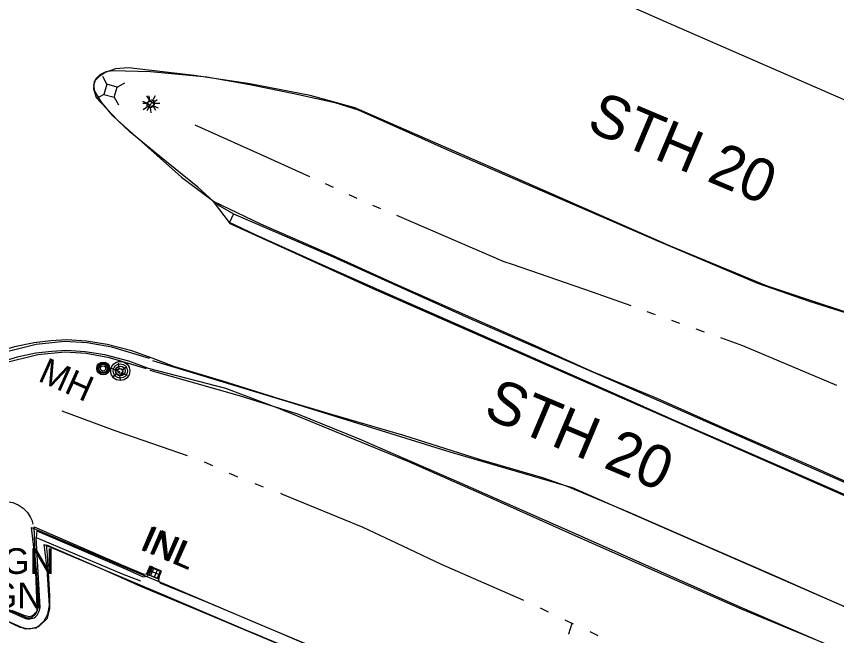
# Model space of a CAD drawing. Extents: x 588843 to 2552415, y 180129 to 269402.
# Drawn here: x 594846.6 to 595038, y 185001.1 to 185145.6 of the extents above; entities that cross this region are included whole.
import ezdxf

# ---------------------------------------------------------------- set-up
doc = ezdxf.new("R2010")
doc.units = 0
for name, color, linetype in [('Default', 7, 'Continuous'), ('E_DRN', 7, 'Continuous'), ('E_DRN_Text', 7, 'Continuous'), ('E_DWY', 7, 'Continuous'), ('E_LTG', 7, 'Continuous'), ('E_MISCPROP', 7, 'Continuous'), ('E_MISCPROP_Planter', 7, 'Continuous'), ('E_RDWY', 7, 'Continuous'), ('E_RDWY_AsphConc', 7, 'Continuous'), ('E_RDWY_C_and_G', 7, 'Continuous'), ('E_RDWY_Gravel', 7, 'Continuous'), ('E_RDWY_Text', 7, 'Continuous'), ('E_SGN', 7, 'Continuous'), ('E_UTL_AG_Bold', 7, 'Continuous'), ('E_UTL_MH', 7, 'Continuous'), ('E_UTL_MH_Text', 7, 'Continuous'), ('E_WTR_P', 7, 'Continuous')]:
    doc.layers.add(name, color=color, linetype=linetype)

# ---------------------------------------------------------------- blocks, each defined once
blk = doc.blocks.new('INLO')
at = {"layer": 'E_DRN'}
for p, q in [((2, -4), (2, 0)), ((4, -4), (4, 0)), ((6, -2), (0, -2))]:
    blk.add_line(p, q, dxfattribs=at)
blk.add_lwpolyline([(0, -4), (6, -4), (6, 0), (0, 0), (0, -4)], close=True, dxfattribs=at)
blk = doc.blocks.new('INLT_22')
at = {"layer": 'E_DRN_Text'}
blk.add_text('INL', height=12, dxfattribs=at).set_placement((-11.03, -6))
blk = doc.blocks.new('MHO')
at = {"layer": 'Default'}
for centre, radius in [((0.08, -0.12), 3), ((0.08, -0.12), 2.43), ((0.07, -0.15), 1.94), ((0.02, -0.16), 1.21)]:
    blk.add_circle(centre, radius, dxfattribs=at)
blk = doc.blocks.new('MHT')
at = {"layer": 'E_UTL_MH_Text'}
blk.add_text('MH', height=12, dxfattribs=at).set_placement((-9.81, -6))
blk = doc.blocks.new('LPOL')
at = {"layer": 'Default'}
for p, q in [((-4, 0), (-1.5, 0)), ((-0.75, 1.3), (-2, 3.46)), ((0.75, 1.3), (2, 3.46)), ((1.5, 0), (4, 0)), ((-2, -3.46), (-0.75, -1.3)), ((2, -3.46), (0.75, -1.3))]:
    blk.add_line(p, q, dxfattribs=at)
for radius in [1.5, 1.5, 1.5, 0.125]:
    blk.add_circle((0, 0), radius, dxfattribs=at)
blk = doc.blocks.new('BSGN_1')
at = {"layer": 'Default'}
blk.add_text('SIGN', height=12, dxfattribs=at).set_placement((-18.56, -6))
blk = doc.blocks.new('POLE_3')
at = {"layer": 'E_MISCPROP'}
for radius in [14.6, 11, 7.32, 3.66]:
    blk.add_circle((0, 0), radius, dxfattribs=at)
blk = doc.blocks.new('LPOL_4')
at = {"layer": 'E_LTG'}
for p, q in [((-13.1, 0), (-4.9, 0)), ((-2.5, 4.3), (-6.6, 11.4)), ((2.5, 4.3), (6.6, 11.4)), ((4.9, 0), (13.1, 0)), ((-6.6, -11.4), (-2.5, -4.3)), ((6.6, -11.4), (2.5, -4.3))]:
    blk.add_line(p, q, dxfattribs=at)
for radius in [4.92, 4.92, 4.92, 0.41]:
    blk.add_circle((0, 0), radius, dxfattribs=at)
blk = doc.blocks.new('INLT_29_2')
at = {"layer": 'E_DRN_Text'}
blk.add_text('INL', height=39.37, dxfattribs=at).set_placement((-36.2, -19.7))
blk = doc.blocks.new('PED_3')
at = {"layer": 'E_UTL_AG_Bold'}
for p, q in [((-8.2, 8.2), (-17.5, 17.5)), ((8.2, 8.2), (17.5, 17.5)), ((-8.2, -8.2), (-17.5, -17.5)), ((8.2, -8.2), (17.5, -17.5))]:
    blk.add_line(p, q, dxfattribs=at)
blk.add_lwpolyline([(-8.2, -8.2), (8.2, -8.2), (8.2, 8.2), (-8.2, 8.2)], close=True, dxfattribs=at)

msp = doc.modelspace()

# ---------------------------------------------------------------- linework, layer by layer
at = {"layer": 'E_DRN'}
msp.add_lwpolyline([(594878.27, 185016.85), (594880.17, 185016.1), (594879.52, 185014.44), (594877.62, 185015.19)], close=True, dxfattribs=at)
at = {"layer": 'E_DWY'}
for points in [[(594851.32, 185016.44), (594850.15, 185026.3), (594876.17, 185015.26), (594882.3, 185012.69), (594902.2, 185004.23)], [(594842.02, 185005.56), (594847.42, 185003.01), (594849.69, 185002.62), (594851.91, 185003.19), (594853.88, 185005.11), (594854.47, 185007.32), (594854.46, 185010.36), (594853.91, 185019.95), (594853.68, 185022.26), (594866.41, 185016.76), (594875.58, 185012.63)], [(594853.8, 185016.73), (594853.14, 185022.31), (594881.32, 185010.39), (594901.22, 185001.93)], [(594812.39, 184960.2), (594816.48, 184971.63), (594821.65, 184984.69), (594829.53, 185003.63), (594833.21, 185012.2), (594849.12, 185005.19), (594850.27, 185005.27), (594851.11, 185006.05), (594851.57, 185006.94), (594851.86, 185008.3), (594851.32, 185016.44)], [(594814.75, 184959.36), (594818.82, 184970.75), (594823.97, 184983.75), (594831.83, 185002.65), (594834.51, 185008.89), (594848.68, 185002.65), (594851.33, 185002.84), (594853.13, 185004.52), (594853.95, 185006.1), (594854.37, 185008.12), (594853.81, 185016.6)], [(594880.13, 185013.4), (594879.84, 185013.96), (594880.08, 185015.33)], [(594875.58, 185012.63), (594890, 185006.61), (594906.61, 184999.61), (594919.3, 184994.16), (594934.73, 184987.79), (594947.71, 184982.35), (594948.54, 184981.95), (594949.63, 184959.24), (594949.85, 184954.76), (594950.38, 184952.7), (594951.56, 184950.95), (594953.31, 184949.6), (594955.43, 184949.05), (594957.6, 184949.36), (594973.26, 184958.44), (594974.11, 184938.99), (594974.84, 184926.05), (594975.21, 184917.53)], [(594880.13, 185013.4), (594890.96, 185008.92), (594907.59, 185001.91), (594920.27, 184996.47), (594935.69, 184990.1), (594948.74, 184984.63), (594950.96, 184983.54), (594952.13, 184959.36), (594952.34, 184955.13), (594952.69, 184953.74), (594953.41, 184952.68), (594954.43, 184951.89), (594955.58, 184951.59), (594956.77, 184951.76), (594975.58, 184962.67), (594976.6, 184939.12), (594977.34, 184926.17), (594977.71, 184917.64)], [(594902.2, 185004.23), (594928.88, 184993.01), (594946.5, 184985.51), (594951.42, 184983.39), (594952.48, 184955.24), (594952.93, 184953.26), (594953.77, 184951.9), (594955.03, 184951.64), (594956.83, 184951.84), (594961.62, 184954.26), (594975.86, 184962.16), (594977.26, 184932.37)], [(594901.23, 185001.93), (594927.91, 184990.71), (594945.51, 184983.22), (594948.98, 184981.72), (594949.99, 184954.9), (594950.59, 184952.3), (594952.21, 184949.66), (594954.92, 184949.11), (594957.55, 184949.41), (594962.79, 184952.05), (594973.55, 184958.02), (594974.77, 184932.26)]]:
    msp.add_lwpolyline(points, dxfattribs=at)
at = {"layer": 'E_MISCPROP_Planter'}
msp.add_lwpolyline([(594831.77, 185013.9), (594837.81, 185029.35), (594838.62, 185030.36), (594839.59, 185031.22), (594839.59, 185031.22), (594840.52, 185031.78), (594841.53, 185032.14), (594841.53, 185032.14), (594844.01, 185032.45), (594844.01, 185032.45), (594845.78, 185032.17), (594845.78, 185032.17), (594847.07, 185031.6), (594848.23, 185030.8), (594848.23, 185030.8), (594849.19, 185029.82), (594849.94, 185028.66), (594849.94, 185028.66), (594850.21, 185028.01), (594850.21, 185028.01), (594850.44, 185027.07), (594850.44, 185027.07)], dxfattribs=at)
at = {"layer": 'E_RDWY'}
for points in [[(594953.31, 185166.36), (594958.15, 185162.28), (594975.56, 185154.43), (594999.99, 185143.55), (595034.76, 185128.38), (595068.45, 185113.72), (595097.34, 185101.25), (595121.56, 185090.33), (595130.22, 185086.62), (595134.71, 185084.42)], [(594925.9, 185124.17), (594915.18, 185127.16), (594901.1, 185129.86), (594888.15, 185131.83), (594872.8, 185133.66), (594869.76, 185133.4), (594867.37, 185132.55), (594865.85, 185131.55), (594864.81, 185130.42), (594864.64, 185128.73), (594865.28, 185126.7), (594870.22, 185121.39), (594885.15, 185108.11), (594894.17, 185101.33), (594897.33, 185099.5)], [(595049.2, 185029.86), (595032.18, 185037.35), (595016.49, 185044.18), (595000.22, 185051.32), (594985.89, 185057.65), (594969.81, 185064.77), (594952.53, 185072.36), (594931.31, 185081.72), (594915.85, 185088.59), (594902.43, 185094.62), (594896.4, 185097.5), (594892.65, 185102.39), (594888.98, 185105.77), (594880.03, 185112.97), (594873.11, 185118.65), (594869.14, 185122.44), (594866.48, 185125.57), (594864.94, 185128.17), (594864.74, 185129.6), (594865.19, 185131.08), (594866.21, 185132.08), (594867.55, 185132.75), (594869.06, 185133.03), (594877.96, 185132.75), (594891.11, 185131.49), (594901.08, 185129.72), (594911.75, 185127.57), (594920.96, 185125.49), (594926.41, 185123.84), (594947.09, 185114.58), (594965.39, 185106.61), (594983.19, 185098.92), (594996.06, 185093.29), (595008.35, 185088.08), (595019.6, 185083.37), (595031.64, 185079.16), (595047.2, 185074.24)], [(594925.9, 185124.17), (594958.5, 185109.94), (594999.16, 185092.06), (595021.58, 185082.77), (595050.38, 185073.2), (595081.02, 185063.61), (595102.72, 185056.02)], [(594897.33, 185099.5), (594896.3, 185097.34), (594929.83, 185082.12), (594970.2, 185064.32), (595016.88, 185043.89), (595058.26, 185025.7), (595093.29, 185010.35), (595106.31, 185004.68)], [(595050.7, 185003.11), (595036.24, 185009.41), (595021.57, 185015.87), (595005.62, 185022.78), (594989.44, 185029.87), (594975.03, 185035.94), (594969.71, 185037.84), (594954.73, 185042.17), (594937.03, 185047.81), (594919.92, 185052.73), (594908.19, 185056.29), (594894.77, 185060.43), (594883.38, 185063.87), (594878.29, 185065.81)], [(594878.43, 185065.29), (594911.2, 185055.3), (594947.8, 185044), (594976.33, 185035.64), (594988.52, 185030.3), (595035.74, 185009.62), (595076.71, 184991.76), (595101.16, 184980.97)]]:
    msp.add_lwpolyline(points, dxfattribs=at)
at = {"layer": 'E_RDWY_AsphConc'}
msp.add_lwpolyline([(594833.35, 185012.01), (594848.19, 185005.26), (594849.04, 185004.96), (594849.04, 185004.96), (594849.76, 185004.95), (594849.76, 185004.95), (594850.81, 185005.24), (594850.81, 185005.24), (594851.2, 185005.5), (594851.2, 185005.5), (594851.46, 185005.82), (594851.46, 185005.82), (594851.8, 185006.42), (594851.8, 185006.42), (594852.01, 185006.93), (594852.01, 185006.93), (594852.15, 185007.6), (594852.15, 185007.6), (594851.28, 185023.97)], dxfattribs=at)
at = {"layer": 'E_RDWY_C_and_G'}
for points in [[(594877.71, 185065.75), (594868.91, 185068.38), (594863.17, 185069.42), (594857.86, 185069.72), (594851.23, 185069.06), (594842.77, 185066.96), (594836.57, 185064.64), (594831.24, 185061.78), (594825.72, 185057.68), (594821.03, 185053.11), (594817.27, 185048.39), (594814.12, 185043.28), (594804.83, 185024.13)], [(594878.29, 185065.81), (594873.6, 185067.51), (594867.78, 185069.05), (594862.98, 185069.84), (594858.38, 185070.11), (594854.67, 185069.92), (594850.77, 185069.44), (594846.17, 185068.46), (594841.35, 185067.05), (594836.8, 185065.31), (594832.22, 185062.74), (594827.91, 185059.98), (594823.46, 185056.1), (594821.34, 185053.95)], [(594876.99, 185063.36), (594868.33, 185065.95), (594862.88, 185066.94), (594857.91, 185067.21), (594851.66, 185066.59), (594843.51, 185064.57), (594837.6, 185062.36), (594832.59, 185059.66), (594827.35, 185055.77), (594822.89, 185051.43), (594819.32, 185046.95), (594816.31, 185042.07), (594807.08, 185023.04)], [(594877.44, 185063.46), (594872.86, 185065.12), (594867.26, 185066.6), (594862.7, 185067.35), (594858.36, 185067.61), (594854.89, 185067.43), (594851.18, 185066.97), (594846.78, 185066.03), (594842.15, 185064.67), (594837.86, 185063.04), (594833.51, 185060.59), (594829.41, 185057.97), (594824.3, 185052.6)], [(594845.5, 185006.96), (594848.37, 185005.84), (594848.37, 185005.84), (594849.29, 185005.56), (594849.29, 185005.56), (594849.67, 185005.51), (594849.67, 185005.51), (594850.07, 185005.59), (594850.07, 185005.59), (594850.75, 185006.01), (594850.75, 185006.01), (594851.1, 185006.34), (594851.1, 185006.34), (594851.38, 185006.72), (594851.38, 185006.72), (594851.51, 185007.09), (594851.51, 185007.09), (594851.5, 185007.65), (594851.5, 185007.65), (594850.82, 185026.43), (594871.59, 185017.42), (594876.35, 185015.43), (594877.05, 185015.5), (594877.05, 185015.5), (594877.55, 185015.89), (594877.55, 185015.89), (594878.05, 185017.25), (594878.38, 185017.15)], [(594851.41, 185025.5), (594851.28, 185023.97), (594871.32, 185015.46), (594875.57, 185013.82)], [(594851.41, 185025.5), (594871.71, 185016.79), (594876.25, 185014.79), (594877.18, 185014.91), (594877.18, 185014.91), (594877.8, 185015.54), (594877.8, 185015.54), (594878.1, 185016.19), (594878.38, 185017.15)]]:
    msp.add_lwpolyline(points, dxfattribs=at)
at = {"layer": 'E_RDWY_Gravel'}
for points in [[(595048.4, 185033.3), (595032.11, 185040.59), (595011.9, 185049.39), (594996.16, 185056.38), (594980.77, 185062.83), (594966.82, 185069.09), (594952.68, 185075.32), (594935.11, 185083.12), (594920.43, 185089.79), (594903.67, 185097.13), (594892.65, 185102.39)], [(594897.33, 185099.5), (594919.84, 185089.79), (594952.31, 185075.17), (594998.39, 185055.12), (595039.68, 185036.96), (595083.25, 185017.84), (595107.08, 185007.74)], [(595052.68, 184991.66), (595035.98, 184998.92), (595015.83, 185007.26), (594997.64, 185015.28), (594976.31, 185024.69), (594956.73, 185033.45), (594938.19, 185041.65), (594920.92, 185048.72), (594907.85, 185054.11), (594895.48, 185058.78), (594877.44, 185063.46)], [(594877.78, 185063.02), (594898.63, 185057.15), (594912.24, 185052.85), (594926.64, 185046.99), (594949.85, 185036.86), (594978.4, 185024.29), (595015.45, 185007.75), (595046.08, 184994.58), (595082.47, 184978.64), (595101.48, 184970.64)]]:
    msp.add_lwpolyline(points, dxfattribs=at)
at = {"layer": 'E_WTR_P'}
for points in [[(594888.31, 185120.33), (594905.09, 185112.76), (594915.02, 185108.25)], [(594918.7, 185106.58), (594920.54, 185105.74)], [(594924.22, 185104.07), (594926.06, 185103.23)], [(594929.75, 185101.58), (594931.61, 185100.78)], [(594935.32, 185099.19), (594960.38, 185088.44), (594962.31, 185087.77)], [(594962.31, 185087.77), (594980.97, 185081.32), (594989.98, 185078.1)], [(594993.78, 185076.74), (594995.28, 185076.2), (594995.69, 185076.06)], [(594999.5, 185074.7), (595001.4, 185074.03)], [(595005.21, 185072.67), (595007.12, 185072)], [(595010.93, 185070.65), (595016.1, 185068.81), (595038.03, 185059.51)], [(594857.26, 185053.51), (594869.61, 185048.97), (594882.47, 185044.49), (594886.46, 185043.13)], [(594890.47, 185041.66), (594892.42, 185040.77)], [(594896.3, 185038.99), (594897.23, 185038.56), (594898.27, 185038.16)], [(594902.26, 185036.6), (594904.25, 185035.83)], [(594908.23, 185034.28), (594908.88, 185034.02), (594927.47, 185026.4), (594936.7, 185022.03)], [(594936.7, 185022.03), (594945.76, 185017.75), (594964.96, 185009.32)], [(594968.84, 185007.51), (594970.76, 185006.59)], [(594974.62, 185004.75), (594976.55, 185003.82)], [(594975.53, 185001.42), (594975.53, 185001.5), (594976.32, 185003.93)], [(594980.41, 185001.98), (594982.33, 185001.06), (594982.34, 185001.06)]]:
    msp.add_lwpolyline(points, dxfattribs=at)

# ---------------------------------------------------------------- block references
at = {"layer": 'E_DRN', "xscale": 0.5, "yscale": 0.5, "rotation": 157.10065989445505}
msp.add_blockref('INLO', (594879.74, 185014.3), dxfattribs=at)
at = {"layer": 'E_DRN_Text'}
for name, p, xscale, yscale, rotation in [('INLT_29_2', (594881.45, 185021.88), 0.1524003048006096, 0.1524003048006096, -22.831300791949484), ('INLT_22', (594881.8, 185021.88), 0.49999999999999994, 0.49999999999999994, -24.085783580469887)]:
    msp.add_blockref(name, p, dxfattribs=dict(at, xscale=xscale, yscale=yscale, rotation=rotation))
at = {"layer": 'E_LTG'}
for name, p, xscale, yscale, rotation in [('LPOL', (594877.87, 185125.07), 0.5, 0.5, -23.807133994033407), ('LPOL_4', (594878.13, 185125.38), 0.15240030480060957, 0.15240030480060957, 0.8014450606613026), ('LPOL', (594870.69, 185062.65), 0.49999999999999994, 0.49999999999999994, -24.085783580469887)]:
    msp.add_blockref(name, p, dxfattribs=dict(at, xscale=xscale, yscale=yscale, rotation=rotation))
at = {"layer": 'E_MISCPROP', "xscale": 0.15240030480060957, "yscale": 0.15240030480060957, "rotation": 0.8014450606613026}
msp.add_blockref('POLE_3', (594870.88, 185062.84), dxfattribs=at)
at = {"layer": 'E_SGN', "xscale": 0.5, "yscale": 0.5}
for p in [(594845.19, 185018.46), (594842.29, 185010.45)]:
    msp.add_blockref('BSGN_1', p, dxfattribs=at)
at = {"layer": 'E_UTL_AG_Bold', "xscale": 0.1524003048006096, "yscale": 0.1524003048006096, "rotation": -15.969778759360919}
msp.add_blockref('PED_3', (594868.61, 185128.28), dxfattribs=at)
at = {"layer": 'E_UTL_MH', "xscale": 0.49999999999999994, "yscale": 0.49999999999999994, "rotation": -24.085783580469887}
msp.add_blockref('MHO', (594866.88, 185063.51), dxfattribs=at)
at = {"layer": 'E_UTL_MH_Text', "xscale": 0.49999999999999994, "yscale": 0.49999999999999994, "rotation": -24.085783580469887}
msp.add_blockref('MHT', (594857.14, 185061.37), dxfattribs=at)

# ---------------------------------------------------------------- texts
at = {"layer": 'E_RDWY_Text'}
for p in [(594979.37, 185119.16), (594955.28, 185052.24)]:
    msp.add_text('STH 20', height=10, rotation=337.1357, dxfattribs=at).set_placement(p)

doc.saveas('drawing.dxf')
